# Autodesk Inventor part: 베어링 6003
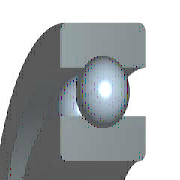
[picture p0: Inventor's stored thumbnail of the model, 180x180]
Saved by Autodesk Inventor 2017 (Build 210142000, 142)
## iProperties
Created: 2012-02
Part Number: 베어링 6003
Material: 강철, 연강
Description: 깊은 그루브 볼 베어링
Document SubType Name: Modeling
Standard: KS B 2023
Designer: mduedu
Standards Organization: KS
Language: ko-KR
Size Designation: 6003 - 17 x 35 x 10
Categories: <MemberInstance><Categories><Category DisplayName="샤프트 부품" InternalName="7f7aeb1f-a693-4053-b835-cee3144e0d98" Mnemonic="SHFT"><Category DisplayName="베어링" Inter
Density: 7.86 g/cm^3
Appearance: 노란색
Mass: 39.0276 g
Surface Area: 48.7538 cm^2
Volume: 4.96535 cm^3
IsCustomPart: 1
Author: mduedu
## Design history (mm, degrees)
sketch "스케치" dims "d0" = 4.68 (= -0.26 x WD + 0.26 x BD)
  geometry: L1 (2.66, 13)-(7.34, 13); L2 (5, 13)-(5, 10.66); L3 (5, 13)-(5, 15.34); L4 (3.261, 11.434)-(0, 11.434); L5 (0, 8.5)-(10, 8.5); L6 (3.261, 14.566)-(0, 14.566); L7 (0, 17.5)-(10, 17.5); L8 (10, 8.5)-(10, 11.434); L9 (6.739, 11.434)-(10, 11.434); L10 (6.739, 14.566)-(10, 14.566); L11 (10, 17.5)-(10, 14.566); L12 (-1.4, 0)-(8.4, 0) reference; L13 (0, -0.3)-(0, 5.3) reference
  constraints: 22 end point, 4 point on line, 2 collinear, 2 perpendicular, 2 symmetric about line, 1 midpoint, 1 parallel, 14 other
  dimensions: "d9" = 17 diameter of L5 L12 (= WD); "d11" = 35 diameter of L7 L12 (= BD); "d12" = 10 distance between parallel lines of L8 L13 (= KB); "d13" = 22.868 diameter of L9 L12 (= 0.326 x BD + 0.674 x WD)
revolve "본체" stored, may be unused: angle "d6" = 90 deg
revolve "볼" stored, may be unused: angle "d7" = 90 deg
pattern_circular "IDS_ARRAYBALL[SIMPL:T]" dims angle "d3" = 360 deg
body "Solid1"
fillet "모깎기1" dims "d1" = 0.3 (= KRS)
other parameters: "WD" = 17 [user parameter; used in 5 equation terms], "BD" = 35 [user parameter; used in 5 equation terms], "KB" = 10 [user parameter; used in 1 equation term], "KRS" = 0.3 [user parameter; used in 1 equation term], "d4" = 0, "d5" = 0, "d8" = 0, "d14" = 0, "d15" = 0, "BBA" = 0 [user parameter], "BC0" = 3250000 [user parameter], "BC" = 6050000 [user parameter], "BR" = 17.5 (= 0.5 x BD) [user parameter], "WR" = 8.5 (= 0.5 x WD) [user parameter]
